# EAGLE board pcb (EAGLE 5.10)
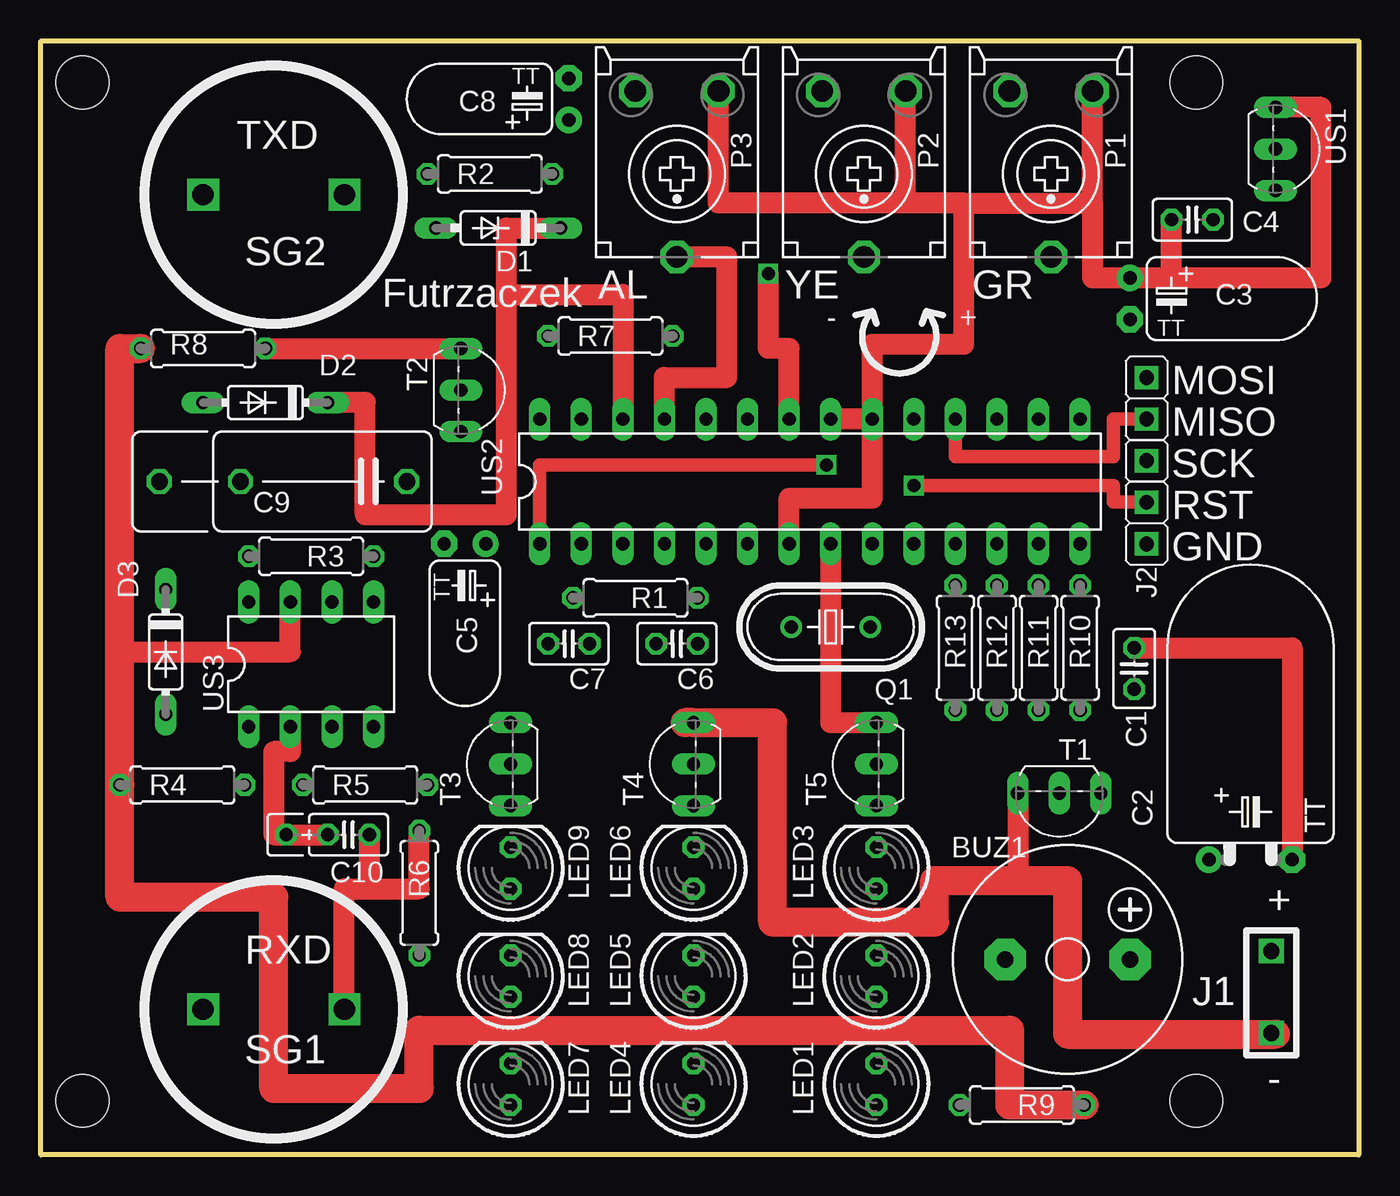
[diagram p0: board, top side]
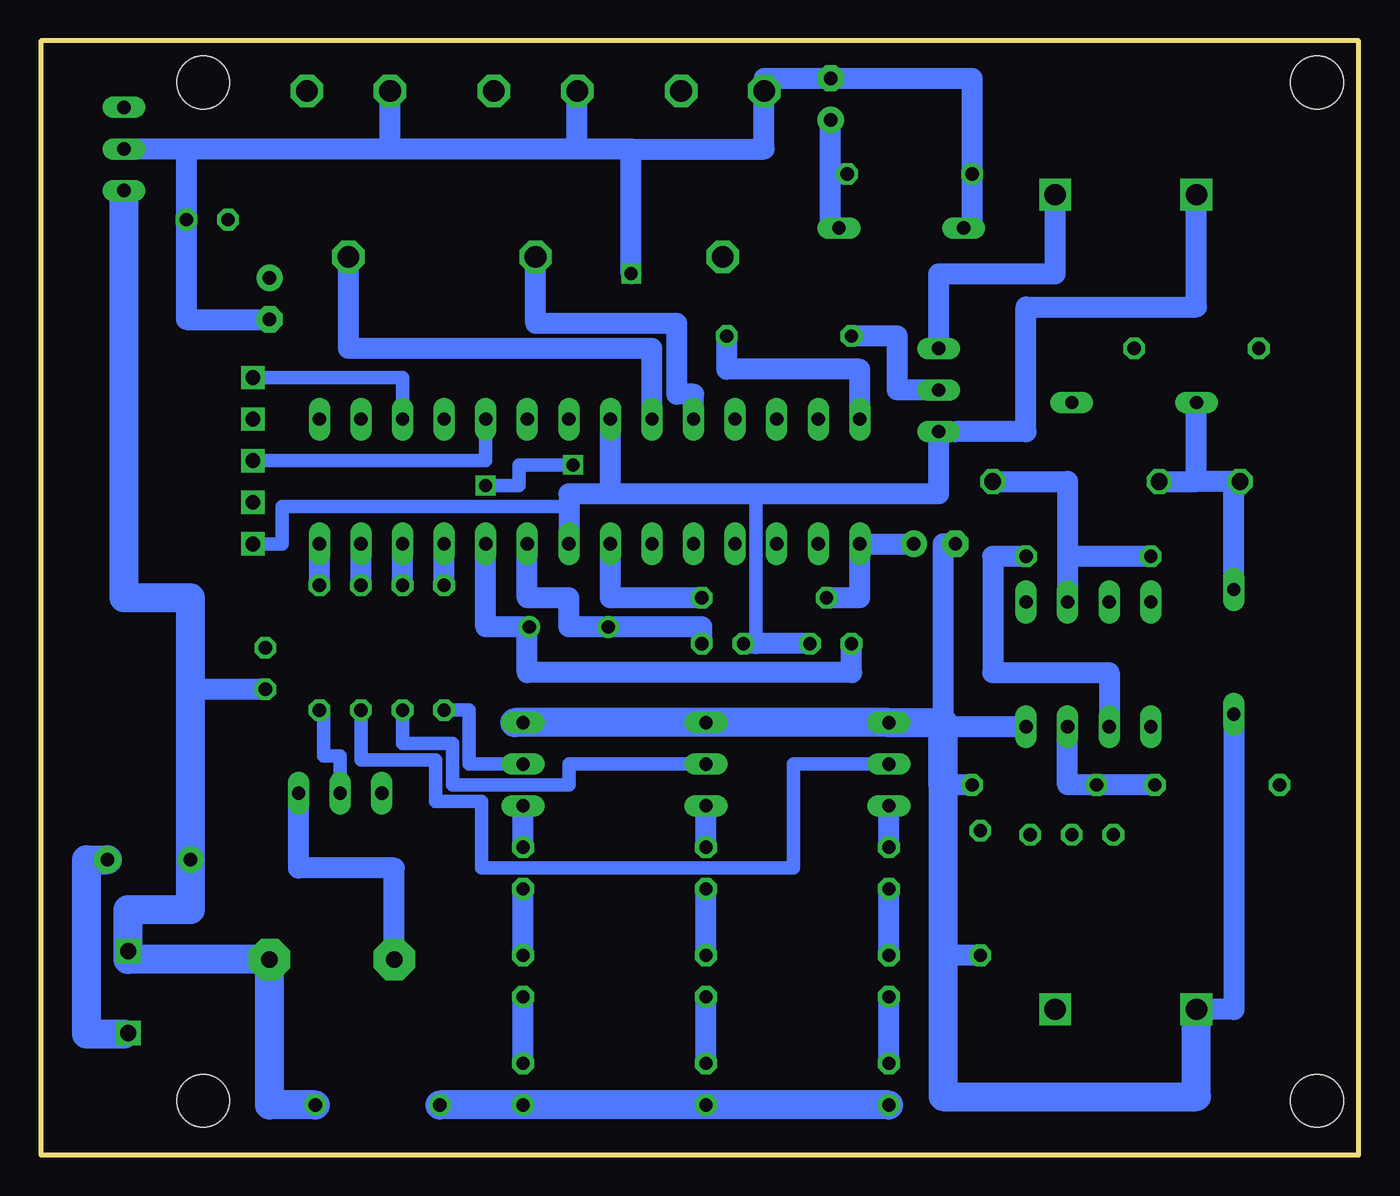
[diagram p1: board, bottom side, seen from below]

Size 80.52 x 68.07 mm. Coordinates in mm from the lower left corner, seen from the top.
Outline: 0,68.07 80.52,68.07 80.52,0 0,0 0,68.07
Copper layers (1*16): Top 0.035mm / dielectric 1.5mm / Bottom 0.035mm
Design rules "default": minimum track width 10mil, minimum drill 24mil, track to track 8mil, track to pad 8mil, pad to pad 8mil, via to via 8mil, smd to smd 8mil, copper to edge 40mil, drill to drill 8mil, minimum pad ring 10mil, minimum via ring 8mil, stop-mask expansion 4mil, vias tented up to drill 0mil, thermal gap 10mil
Holes 3.2 mm at 2.54,65.53 70.61,65.53 2.54,3.3 70.61,3.3

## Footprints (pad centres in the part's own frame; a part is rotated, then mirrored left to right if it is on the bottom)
F/CM12P = drill 1.016 pad 2.54 octagon: + 3.81,0; - -3.81,0
C025-025X050 = drill 0.813 octagon: 1 -1.27,0; 2 1.27,0
TT5D11L = drill 0.813 pad 1.6 round: + -2.54,0 | drill 0.813 pad 1.6 octagon: - 2.54,0
TT2D5L = drill 0.813 pad 1.6 round: + -1.27,0 | drill 0.813 pad 1.6 octagon: - 1.27,0
TT2D4L = drill 0.813 pad 1.6 round: + -1.27,0 | drill 0.813 pad 1.6 octagon: - 1.27,0
C102_152-062X184 = drill 1.016 octagon: 1 -5.08,0; 2 5.08,0; 3 10.033,0
C025_050-025X075 = drill 0.813 octagon: 1 -1.27,0; 2 1.27,0; 3 3.81,0
DO35Z7 = drill 0.813 long: A 3.81,0; C -3.81,0
DO35-7B = drill 0.813 long: A 3.81,0; C -3.81,0
JP1 = drill 0.914 pad 1.422 square: 1 0,-1.27; 2 0,1.27
LED5MM = drill 0.813 octagon: A -1.27,0; K 1.27,0
ECP10S = drill 1.321 octagon: A -2.54,-5.08; E 2.54,-5.08; S 0,5.08
HC49U70 = drill 0.813 round: 1 -2.413,0; 2 2.413,0
0207/7 = drill 0.813 octagon: 1 -3.81,0; 2 3.81,0
TO92- = drill 0.813 long: 1 2.54,0; 2 0,0; 3 -2.54,0
DIL28-3 = drill 0.813 long: 1 -16.51,-3.81; 2 -13.97,-3.81; 3 -11.43,-3.81; 4 -8.89,-3.81; 5 -6.35,-3.81; 6 -3.81,-3.81; 7 -1.27,-3.81; 8 1.27,-3.81; 9 3.81,-3.81; 10 6.35,-3.81; 11 8.89,-3.81; 12 11.43,-3.81; 13 13.97,-3.81; 14 16.51,-3.81; 15 16.51,3.81; 16 13.97,3.81; 17 11.43,3.81; 18 8.89,3.81; 19 6.35,3.81; 20 3.81,3.81; 21 1.27,3.81; 22 -1.27,3.81; 23 -3.81,3.81; 24 -6.35,3.81; 25 -8.89,3.81; 26 -11.43,3.81; 27 -13.97,3.81; 28 -16.51,3.81
DIL08 = drill 0.813 long: 1 -3.81,-3.81; 2 -1.27,-3.81; 3 1.27,-3.81; 4 3.81,-3.81; 5 3.81,3.81; 6 1.27,3.81; 7 -1.27,3.81; 8 -3.81,3.81

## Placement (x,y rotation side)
BUZ1  [F/CM12P]  62.74,11.94 0 top
C1  [C025-025X050]  66.8,29.72 90 top
C2  [TT5D11L]  73.91,18.03 0 top
C3  [TT2D5L]  66.55,52.32 270 top
C4  [C025-025X050]  70.36,57.15 0 top
C5  [TT2D4L]  25.91,37.34 180 top
C6  [C025-025X050]  38.86,31.24 180 top
C7  [C025-025X050]  32.26,31.24 180 top
C8  [TT2D4L]  32.26,64.52 90 top
C9  [C102_152-062X184]  17.27,41.15 180 top
C10  [C025_050-025X075]  18.8,19.56 180 top
D1  [DO35Z7]  27.94,56.64 180 top
D2  [DO35-7B]  13.72,45.97 180 top
D3  [DO35-7B]  7.62,30.73 270 top
E$40  [JP1]  67.56,46.23 0 top
E$41  [JP1]  67.56,43.69 0 top
E$42  [JP1]  67.56,41.15 0 top
J2  [JP1]  67.56,38.61 0 top
LED1  [LED5MM]  51.05,4.32 90 top
LED2  [LED5MM]  51.05,10.92 90 top
LED3  [LED5MM]  51.05,17.53 90 top
LED4  [LED5MM]  39.88,4.32 90 top
LED5  [LED5MM]  39.88,10.92 90 top
LED6  [LED5MM]  39.88,17.53 90 top
LED7  [LED5MM]  28.7,4.32 90 top
LED8  [LED5MM]  28.7,10.92 90 top
LED9  [LED5MM]  28.7,17.53 90 top
P1  [ECP10S]  61.72,59.94 180 top
P2  [ECP10S]  50.29,59.94 180 top
P3  [ECP10S]  38.86,59.94 180 top
Q1  [HC49U70]  48.26,32.26 180 top
R1  [0207/7]  36.32,34.04 180 top
R2  [0207/7]  27.43,59.94 0 top
R3  [0207/7]  16.51,36.58 180 top
R4  [0207/7]  8.64,22.61 0 top
R5  [0207/7]  19.81,22.61 0 top
R6  [0207/7]  23.11,16 270 top
R7  [0207/7]  34.8,50.04 0 top
R8  [0207/7]  9.91,49.28 0 top
R9  [0207/7]  59.94,3.05 180 top
R10  [0207/7]  63.5,30.99 270 top
R11  [0207/7]  60.96,30.99 270 top
R12  [0207/7]  58.42,30.99 270 top
R13  [0207/7]  55.88,30.99 270 top
T1  [TO92-]  62.23,22.1 180 top
T2  [TO92-]  25.65,46.74 270 top
T3  [TO92-]  28.7,23.88 90 top
T4  [TO92-]  39.88,23.88 90 top
T5  [TO92-]  51.05,23.88 90 top
US1  [TO92-]  75.44,61.47 270 top
US2  [DIL28-3]  46.99,41.15 0 top
US3  [DIL08]  16.51,29.97 0 top

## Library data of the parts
BUZ1 = buzzer
C1-C10 R1-R13 = rcl
D1-D3 = diode
E$40-E$42 J2 = hybrid
LED1-LED9 = led
P1-P3 = pot
Q1 = crystal
T1-T5 US1 = transistor-npn
US2 US3 = 40xx

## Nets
S$1: R7.2
S$2: C6.2 C7.1
S$3: C6.1
S$5: E$40.2 US2.17
S$6: C7.2 US2.10
S$7: R13.1
S$8: R12.1 US2.12
S$9: R11.1 US2.13
S$10: R10.1 US2.14
S$11: LED9.K
S$12: LED8.K LED9.A
S$13: LED7.K LED8.A
S$14: LED6.K
S$15: LED5.K LED6.A
S$16: LED4.K LED5.A
S$17: LED3.K
S$18: LED2.K LED3.A
S$19: LED1.K LED2.A
S$21: R13.2 T5.2
S$22: R12.2 T4.2
S$23: R11.2 T3.2
S$24: R10.2 T1.2
S$25: E$42.1 R1.2 US2.1
S$26: BUZ1.- T1.3
S$27: T1.1
S$28: C10.1 R6.1
S$29: E$40.1 US2.18
S$30: E$41.1 US2.19
S$31: D1.C D2.C
S$32: P2.A
S$33: T4.1
S$35: C1.1
S$36: P2.S US2.24
S$37: P1.S US2.23
S$39: P3.S
S$40: C9.2 D3.C
S$41: US3.4
S$42: R4.2 US3.3
S$43: C10.2
S$45: LED7.A R9.2
S$46: R6.2
S$47: C5.-
S$48: C9.1 R3.2 US3.6
S$49: R3.1
S$50: C8.+ R2.2
S$51: C1.2 C2.-
S$52: D3.A R5.2 T3.1
S$53: T2.3
S$55: C3.+ C4.1 P1.A P3.A R1.1 US1.3 US2.7 US2.20 US2.21
S$56: C3.- C4.2 C8.- J2.1 P1.E P2.E P3.E R2.1 T2.1 US1.2 US2.8 US2.22
S$57: BUZ1.+ C2.+ R4.1 R8.1 R9.1 US1.1 US3.7

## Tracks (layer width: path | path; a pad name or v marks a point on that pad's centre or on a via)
S$1
  Bottom 1.27: 30.48,44.7 30.48,48.01 38.61,48.01 R7.2
S$2
  Bottom 0.813: 36.83,31.24 36.83,40.13
  Bottom 1.27: C7.1 36.83,31.24 C6.2
S$3
  Bottom 1.27: 50.8,37.08 50.8,34.04 48.26,34.04 48.26,32.26 40.13,32.26 C6.1
S$4
  Bottom 1.27: 30.99,50.04 28.19,50.04 28.19,46.74 25.15,46.74
S$5
  Bottom 0.813: E$40.2 58.42,47.5 US2.17
S$6
  Bottom 1.27: C7.2 30.99,29.46 50.8,29.46 50.8,32.26 53.34,32.26 US2.10
S$7
  Bottom 1.27: R13.1 55.88,37.59
S$8
  Bottom 1.27: R12.1 US2.12
S$9
  Bottom 1.27: R11.1 US2.13
S$10
  Bottom 1.27: R10.1 US2.14
S$11
  Bottom 1.27: LED9.K 28.7,21.08
S$12
  Bottom 1.27: LED8.K LED9.A
S$13
  Bottom 1.27: LED7.K LED8.A
S$14
  Bottom 1.27: LED6.K 39.88,21.08
S$15
  Bottom 1.27: LED5.K LED6.A
S$16
  Bottom 1.27: LED4.K LED5.A
S$17
  Bottom 1.27: LED3.K 51.05,21.08
S$18
  Bottom 1.27: LED2.K LED3.A
S$19
  Bottom 1.27: LED1.K LED2.A
S$21
  Bottom 0.813: T5.2 54.36,23.88 54.36,27.18 R13.2
S$22
  Bottom 0.813: T4.2 48.26,23.88 48.26,22.61 55.37,22.61 55.37,25.15 58.42,25.15 R12.2
S$23
  Bottom 0.813: T3.2 34.54,23.88 34.54,17.53 53.59,17.53 53.59,21.59 56.39,21.59 56.39,24.13 60.96,24.13 R11.2
S$24
  Bottom 0.813: R10.2 63.25,27.18 63.25,24.38 62.23,24.38 T1.2
S$25  (via drill 0.8)
  Top 0.813: E$42.1 65.53,39.88 65.53,40.89 v53.34,40.89 | v48.01,42.16 30.48,42.16 US2.1 30.48,37.59
  Bottom 0.813: v53.34,40.89 51.31,40.89 51.31,42.16 v48.01,42.16
  Bottom 1.27: 27.18,37.34 US2.1 30.48,34.04 R1.2
S$26
  Bottom 1.27: BUZ1.- 58.93,17.53 64.77,17.53 T1.3
S$27
  Top 1.27: T1.1 59.69,16.51
S$28  (via drill 1.3)
  Top 1.27: v18.54,8.89 18.54,16.26 20.07,16.26 | 20.07,16.26 23.11,16.26 R6.1 | C10.1 20.07,16.26
S$29
  Top 0.813: E$40.1 65.53,44.96 65.53,42.67 55.88,42.67 US2.18
S$30
  Bottom 0.813: E$41.1 53.34,42.42 US2.19
S$31
  Top 1.27: 35.56,44.45 35.56,52.58 28.45,52.58 | 28.45,52.58 28.45,56.64 D1.C | 28.45,52.58 28.45,39.12 19.81,39.12 19.81,45.97 D2.C
S$32
  Top 1.27: 52.83,58.17 P2.A
S$33
  Top 1.778: 75.44,7.37 62.74,7.37 62.74,16.76 54.61,16.76 54.61,14.22 44.7,14.22 44.7,26.42 T4.1 39.37,26.42
S$34
  Bottom 1.27: 9.91,58.67 9.91,51.82 20.32,51.82 20.32,44.2 24.64,44.2
S$35
  Bottom 1.27: C1.1 71.12,28.45
S$36
  Bottom 1.27: P2.S 50.29,50.8 41.66,50.8 41.66,46.48 40.64,46.48 US2.24
S$37
  Bottom 1.27: US2.23 43.18,49.28 61.72,49.28 P1.S
S$38  (via drill 1)
  other vias: 75.18,7.45
S$39
  Top 1.27: P3.S 41.91,54.86 41.91,47.5 38.1,47.5 38.1,44.7
S$40
  Bottom 1.27: 7.37,41.15 7.62,41.15 | 7.62,41.15 9.91,41.15 | C9.2 9.91,41.15 | 9.91,41.15 9.91,45.97 | D3.C 7.62,41.15
S$41
  Bottom 1.27: US3.4 25.4,26.16
S$42
  Bottom 1.27: R4.2 17.78,22.61 US3.3
S$43
  Top 1.27: 15.24,25.91 15.24,24.64 14.22,24.64 14.22,19.56 C10.2
S$44  (via drill 1.3)
  other vias: 18.54,58.67
S$45
  Bottom 1.778: LED7.A R9.2
S$46
  Bottom 1.27: R6.2 24.89,12.19
S$47
  Bottom 1.27: C5.- 25.4,37.34 25.4,26.67
S$48
  Bottom 1.27: C9.1 17.78,41.15 17.78,36.58 | 17.78,36.58 US3.6 | R3.2 17.78,36.58
S$49
  Bottom 1.27: R3.1 22.35,36.58 22.35,29.46 15.24,29.46 15.24,25.91
S$50
  Bottom 1.27: 32.26,59.94 R2.2 | 32.26,59.94 C8.+ | 32.26,59.94 32.26,56.64 31.5,56.64
S$51
  Top 1.27: C1.2 76.45,30.99 C2.-
  Bottom 1.27: 75.44,7.37 75.18,7.37
  Bottom 1.778: C2.- 77.72,18.03 77.72,7.37 75.44,7.37
S$52  (via drill 1.3)
  Bottom 1.27: D3.A 7.62,8.89 v9.91,8.89 | T3.1 25.65,26.42 25.65,22.61 R5.2
  Bottom 1.778: T3.1 28.19,26.42 | T3.1 51.56,26.42 | T3.1 25.4,26.42 25.4,3.56 9.91,3.56 v9.91,8.89
S$53
  Top 1.27: 13.72,49.28 T2.3
  Bottom 1.27: 18.54,58.67 18.54,53.85 25.65,53.85 T2.3
S$54  (via drill 1.3)
  other vias: 9.91,58.67
S$55
  Top 1.27: 64.26,58.17 P1.A | 64.26,58.17 64.26,53.59 C3.+ 69.09,53.59 | P3.A 41.4,58.17 56.39,58.17 | 56.39,58.17 64.26,58.17 | 56.39,58.17 56.39,49.53 50.8,49.53 US2.20 | US2.20 US2.21 | US2.20 50.8,40.13 45.72,40.13 US2.7 | 69.09,53.59 78.23,53.59 78.23,64.01 US1.3 | 69.09,53.59 C4.1
  Bottom 1.27: US2.7 45.72,34.04 R1.1
S$56  (via drill 0.8)
  Top 1.27: v44.45,53.85 44.45,49.28 45.72,49.28 US2.22 | US2.8 48.26,26.42 51.31,26.42
  Bottom 0.813: J2.1 65.79,37.34 65.79,39.62 48.26,39.62
  Bottom 1.27: 23.88,56.64 23.62,56.64 R2.1 23.62,65.79 C8.- 36.32,65.79 P3.E 36.32,61.47 44.45,61.47 | C3.- 71.63,51.05 C4.2 71.63,61.47 | 71.63,61.47 US1.2 | 59.18,61.47 P1.E | 59.18,61.47 71.63,61.47 | 47.75,61.47 P2.E | 47.75,61.47 59.18,61.47 | 44.45,61.47 47.75,61.47 | v44.45,53.85 44.45,61.47 | US2.8 48.26,39.62 48.26,40.39 45.72,40.39 | 45.72,40.39 US2.22 | 45.72,40.39 25.65,40.39 T2.1
S$57  (via drill 1)
  Top 1.27: US3.7 15.24,30.73 4.83,30.73
  Top 1.778: R8.1 4.83,49.28 4.83,30.73 R4.1 4.83,15.75 14.22,15.75 14.22,4.06 23.11,4.06 23.11,7.62 59.18,7.62 59.18,3.05 R9.1
  Bottom 1.27: 75.44,58.67 US1.1 | 66.55,11.68 BUZ1.+
  Bottom 1.778: 75.44,58.67 75.44,34.04 71.37,34.04 C2.+ 71.37,14.99 75.18,14.99 v75.18,12.45 75.18,11.94 BUZ1.+ | 66.55,11.68 66.55,3.05 R9.1

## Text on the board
tNames: TXD | SG2 | Futrzaczek | AL | YE | GR | - | + | MOSI | MISO | SCK | RST | GND | + | RXD | J1 | SG1 | -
